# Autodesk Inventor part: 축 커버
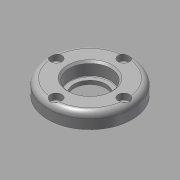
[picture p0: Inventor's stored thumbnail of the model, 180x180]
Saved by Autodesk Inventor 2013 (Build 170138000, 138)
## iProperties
Created: 2015-10
Part Number: 축 커버
Document SubType Name: Modeling
Designer: mdu
Density: 1 g/cm^3
Material: 강철, 연강
Mass: 9.68563 g
Surface Area: 48.0703 cm^2
Volume: 9.68563 cm^3
Author: mdu
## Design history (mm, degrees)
sketch "스케치1"
  geometry: C1 r 22.355 at (0, 0) reference; C2 r 14 at (0, 0) reference; C3 r 1.23 at (0, 18) reference; 1 further point
extrude "돌출1" new body sketch "스케치1" distance "d0" = 8; taper "d1" = 0 deg
sketch "스케치2"
  geometry: C1 r 14 at (0, 0) reference; 1 further point
extrude "돌출2" join sketch "스케치2" distance "d2" = 3; taper "d3" = 0 deg
hole "구멍1" diameter "d6" = 17; stored, may be unused: countersink angle "d10" = 90 deg, drill point angle "d12" = 118 deg; dims "d4" = 10, "d5" = 10, "d7" = 6, "d8" = 23, "d9" = 2, "d11" = 8
hole "구멍2" diameter "d15" = 22; stored, may be unused: countersink angle "d19" = 90 deg, drill point angle "d21" = 0 deg; dims "d13" = 10, "d14" = 10, "d16" = 6, "d17" = 25, "d18" = 2, "d20" = 7
fillet "모깎기1" dims "d22" = 3, "d23" = 0.3
chamfer "모따기1" distance "d24" = 1; stored, may be unused: second distance "d25" = 2, angle "d26" = 45 deg
sketch "스케치3"
  geometry: 2 further points
hole "구멍3" sketch "스케치3" at (0, 18) diameter "d27" = 3.4; stored, may be unused: countersink angle "d31" = 90 deg, drill point angle "d33" = 118 deg; dims "d28" = 6, "d29" = 6, "d30" = 3.3, "d32" = 7
node "솔리드1"
pattern_circular "원형 패턴1" dims angle "d35" = 360 deg
node "참조1"
node "참조2"
node "참조3"
